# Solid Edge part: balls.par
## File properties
Accuracy: 0.99
Title: Bearing
Author: Abhinav Rai
Template: Normal.par
Last saved by: Rajat Kamboj
Revision: 11
Application: Solid Edge
Material: aluminum
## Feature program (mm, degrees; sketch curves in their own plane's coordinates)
sketch for "unnamed RevolvedProtrusion 1" plane through (0, 0, 0) normal (0, -1, 0) x-axis (1, 0, 0)
  arc centre (0, 0) radius 6.604 from (0, 6.604) to (0, -6.604) cw
  line (0, 6.604) -> (0, -6.604)
revolve "unnamed RevolvedProtrusion 1" add full turn 360 deg
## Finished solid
Body 1: solid body, 1 face, 0 edges, 0 vertices.
  Faces by surface: sphere 1
Spherical faces by radius (mm): R6.604 x1
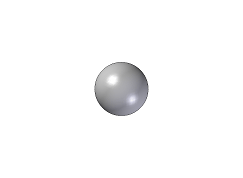
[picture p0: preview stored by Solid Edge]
